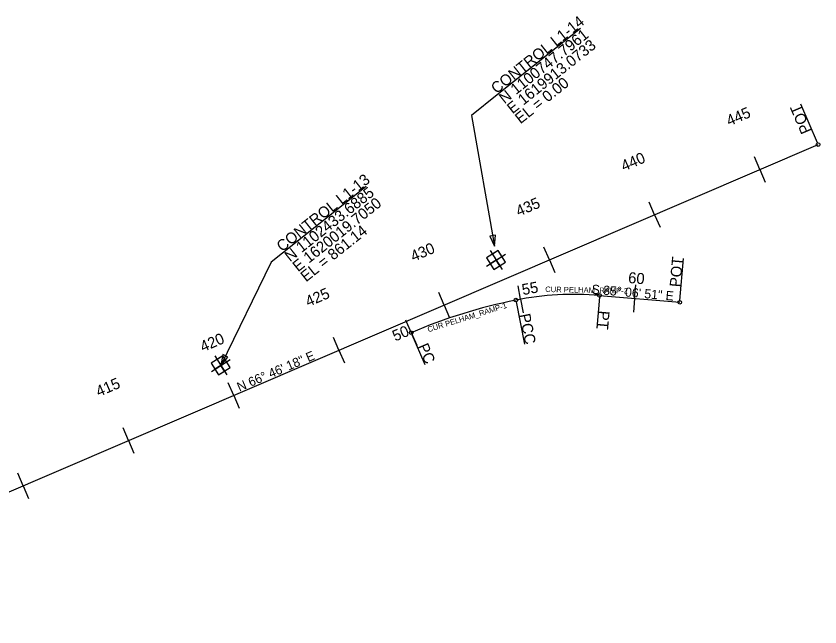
# Model space of a CAD drawing. Extents: x 1603447 to 1622636, y 1083818 to 1103958.
# Drawn here: x 1619126 to 1622636, y 1101292 to 1103958 of the extents above; entities that cross this region are included whole.
import ezdxf

# ---------------------------------------------------------------- set-up
doc = ezdxf.new("R2010")
doc.units = 0
for name, color, linetype in [('Level 1', 7, 'Continuous'), ('RD_HC_Points', 7, 'Continuous'), ('RD_HC_SUR_Bearing_TX400', 7, 'Continuous'), ('RD_HC_SUR_CL400', 7, 'Continuous'), ('RD_HC_SUR_PC_PT_400', 7, 'Continuous'), ('RD_HC_SUR_Tic400', 7, 'Continuous'), ('RD_HC_SUR_TX_Sta400', 7, 'Continuous'), ('RD_SHT_Misc1', 7, 'Continuous'), ('RD_TX_Misc1', 7, 'Continuous')]:
    doc.layers.add(name, color=color, linetype=linetype)

msp = doc.modelspace()

# ---------------------------------------------------------------- linework, layer by layer
at = {"layer": 'RD_HC_Points'}
for p, q in [((1621591, 1103903.8), (1621226.1, 1103613.6)), ((1620654.3, 1103213.8), (1620289.9, 1102924))]:
    msp.add_line(p, q, dxfattribs=at)
for points in [[(1621226.1, 1103613.6), (1621114.4, 1103524.7), (1621215.4, 1102954.1)], [(1620289.9, 1102924), (1620240.2, 1102884.4), (1620019.7, 1102433.7)]]:
    msp.add_lwpolyline(points, dxfattribs=at)
for points in [[(1621195.1, 1102997.6), (1621215.4, 1102954.1), (1621219.6, 1103002)], [(1620028.9, 1102480.8), (1620019.7, 1102433.7), (1620051.2, 1102469.9)]]:
    msp.add_lwpolyline(points, close=True, dxfattribs=at)
at = {"layer": 'RD_HC_SUR_CL400'}
for p, q in [((1617722.6, 1101292.3), (1622627.7, 1103397.5)), ((1621673.4, 1102738.7), (1622023.6, 1102708.8))]:
    msp.add_line(p, q, dxfattribs=at)
for centre, radius, start, end in [((1621562.7, 1101443.5), 1300, 85.1143, 101.2949), ((1621758.5, 1100462.8), 2300, 101.2949, 113.2284)]:
    msp.add_arc(centre, radius, start, end, dxfattribs=at)
at = {"layer": 'RD_HC_SUR_PC_PT_400'}
for p, q in [((1622624.6, 1103404.9), (1622552.2, 1103573.4)), ((1622024.3, 1102716.8), (1622039.9, 1102899.5)), ((1621672.7, 1102730.8), (1621661.2, 1102595.4)), ((1621309.6, 1102710.4), (1621346.4, 1102526.6)), ((1620854.6, 1102569), (1620911.3, 1102436.9))]:
    msp.add_line(p, q, dxfattribs=at)
for centre in [(1622627.7, 1103397.5), (1621308.1, 1102718.3), (1621673.4, 1102738.7), (1622023.6, 1102708.8), (1620851.4, 1102576.4)]:
    msp.add_circle(centre, 8, dxfattribs=at)
at = {"layer": 'RD_HC_SUR_Tic400'}
for p, q in [((1622557.3, 1103367.3), (1622557.3, 1103367.3)), ((1622373.5, 1103288.4), (1622349.8, 1103343.5)), ((1622465.4, 1103327.8), (1622465.4, 1103327.8)), ((1622373.5, 1103288.4), (1622397.2, 1103233.3)), ((1622281.6, 1103249), (1622281.6, 1103249)), ((1622189.7, 1103209.5), (1622189.7, 1103209.5)), ((1621914, 1103091.2), (1621890.4, 1103146.3)), ((1622097.8, 1103170.1), (1622097.8, 1103170.1)), ((1622005.9, 1103130.6), (1622005.9, 1103130.6)), ((1621914, 1103091.2), (1621937.7, 1103036.1)), ((1621822.1, 1103051.8), (1621822.1, 1103051.8)), ((1621730.2, 1103012.3), (1621730.2, 1103012.3)), ((1621638.4, 1102972.9), (1621638.4, 1102972.9)), ((1621454.6, 1102894), (1621430.9, 1102949.1)), ((1621454.6, 1102894), (1621478.2, 1102838.9)), ((1621328.7, 1102722.2), (1621317.9, 1102781.2)), ((1621826.7, 1102725.6), (1621831.8, 1102785.4)), ((1620995.1, 1102696.8), (1620971.4, 1102751.9)), ((1621826.7, 1102725.6), (1621821.6, 1102665.8)), ((1620995.1, 1102696.8), (1621018.8, 1102641.7)), ((1621328.7, 1102722.2), (1621339.5, 1102663.2)), ((1620851.4, 1102576.4), (1620827.8, 1102631.5)), ((1620535.6, 1102499.6), (1620512, 1102554.7)), ((1620719.4, 1102578.5), (1620719.4, 1102578.5)), ((1620851.4, 1102576.4), (1620875.1, 1102521.3)), ((1620627.5, 1102539.1), (1620627.5, 1102539.1)), ((1620535.6, 1102499.6), (1620559.3, 1102444.5)), ((1620443.7, 1102460.2), (1620443.7, 1102460.2)), ((1620351.8, 1102420.7), (1620351.8, 1102420.7)), ((1620259.9, 1102381.3), (1620259.9, 1102381.3)), ((1620076.2, 1102302.4), (1620052.5, 1102357.6)), ((1620168.1, 1102341.9), (1620168.1, 1102341.9)), ((1620076.2, 1102302.4), (1620099.8, 1102247.3)), ((1619984.3, 1102263), (1619984.3, 1102263)), ((1619892.4, 1102223.5), (1619892.4, 1102223.5)), ((1619800.5, 1102184.1), (1619800.5, 1102184.1)), ((1619616.7, 1102105.2), (1619593, 1102160.4)), ((1619708.6, 1102144.7), (1619708.6, 1102144.7)), ((1619616.7, 1102105.2), (1619640.4, 1102050.1)), ((1619524.8, 1102065.8), (1619524.8, 1102065.8)), ((1619432.9, 1102026.3), (1619432.9, 1102026.3)), ((1619341, 1101986.9), (1619341, 1101986.9)), ((1619157.2, 1101908), (1619133.6, 1101963.2)), ((1619249.1, 1101947.5), (1619249.1, 1101947.5)), ((1619157.2, 1101908), (1619180.9, 1101852.9))]:
    msp.add_line(p, q, dxfattribs=at)
at = {"layer": 'RD_SHT_Misc1'}
for p, q in [((1621195.6, 1102934.4), (1621248, 1102852.2)), ((1621180.7, 1102867.1), (1621262.9, 1102919.6)), ((1621205.6, 1102918.6), (1621221.8, 1102893.3)), ((1621221.8, 1102893.3), (1621247.1, 1102909.5)), ((1621221.8, 1102893.3), (1621196.5, 1102877.2)), ((1621237.9, 1102868), (1621221.8, 1102893.3)), ((1619978.6, 1102407.5), (1620060.8, 1102459.9)), ((1619993.5, 1102474.8), (1620045.9, 1102392.6)), ((1620003.6, 1102459), (1620019.7, 1102433.7)), ((1620019.7, 1102433.7), (1620045, 1102449.8)), ((1620019.7, 1102433.7), (1619994.4, 1102417.6)), ((1620035.8, 1102408.4), (1620019.7, 1102433.7))]:
    msp.add_line(p, q, dxfattribs=at)
for points in [[(1621212.6, 1102851.9), (1621263.2, 1102884.2), (1621230.9, 1102934.8), (1621180.4, 1102902.5)], [(1620010.6, 1102392.3), (1620061.1, 1102424.5), (1620028.9, 1102475.1), (1619978.3, 1102442.8)]]:
    msp.add_lwpolyline(points, close=True, dxfattribs=at)
for points in [[(1621247.1, 1102909.5), (1621230.9, 1102934.8), (1621205.6, 1102918.6)], [(1621196.5, 1102877.2), (1621212.6, 1102851.9)], [(1621212.6, 1102851.9), (1621237.9, 1102868)], [(1620045, 1102449.8), (1620028.9, 1102475.1), (1620003.6, 1102459)], [(1619994.4, 1102417.6), (1620010.6, 1102392.3)], [(1620010.6, 1102392.3), (1620035.8, 1102408.4)]]:
    msp.add_lwpolyline(points, dxfattribs=at)

# ---------------------------------------------------------------- texts
at = {"layer": 'Level 1'}
for s, rotation, p in [('445', 23.2284, (1622239.6, 1103476.9)), ('435', 23.2284, (1621320.6, 1103082.5)), ('55', 10.3711, (1621339, 1102740)), ('425', 23.2284, (1620401.7, 1102688.1)), ('415', 23.2284, (1619487, 1102295.5))]:
    msp.add_text(s, height=48, rotation=rotation, dxfattribs=at).set_placement(p)
at = {"layer": 'RD_HC_Points'}
for s, p in [('CONTROL L1-14', (1621223.7, 1103616.8)), ('N 1100747.7961', (1621258.5, 1103572.9)), ('E 1619913.0733', (1621293.4, 1103529.1)), ('EL = 0.00', (1621328.2, 1103485.3)), ('CONTROL L1-13', (1620287.5, 1102927.1)), ('N 1102433.6885', (1620322.3, 1102883.3)), ('E 1620019.7050', (1620357.2, 1102839.5)), ('EL = 861.14', (1620392, 1102795.6))]:
    msp.add_text(s, height=48, rotation=38.4995, dxfattribs=at).set_placement(p)
at = {"layer": 'RD_HC_SUR_Bearing_TX400'}
for s, rotation, p in [('S 85%%d 06\' 51" E', 355.1143, (1621637.7, 1102746.8)), ('N 66%%d 46\' 18" E', 23.2284, (1620101.2, 1102318.6))]:
    msp.add_text(s, height=40, rotation=rotation, dxfattribs=at).set_placement(p)
at = {"layer": 'RD_HC_SUR_PC_PT_400'}
for s, rotation, p in [('POT', 113.2284, (1622600.2, 1103456.5)), ('POT', 85.1143, (1622027.1, 1102773.7)), ('PCC', 281.2949, (1621322.8, 1102654.9)), ('PT', 265.1143, (1621669.9, 1102673.8)), ('PC', 293.2284, (1620878.9, 1102517.4))]:
    msp.add_text(s, height=48, rotation=rotation, dxfattribs=at).set_placement(p)
at = {"layer": 'RD_HC_SUR_TX_Sta400'}
for s, rotation, p in [('440', 23.2284, (1621779.8, 1103279.5)), ('430', 23.2284, (1620860.9, 1102885.2)), ('60', 355.1143, (1621797.1, 1102793.4)), ('50', 23.2284, (1620781.5, 1102537.5)), ('420', 23.2284, (1619942, 1102490.8))]:
    msp.add_text(s, height=48, rotation=rotation, dxfattribs=at).set_placement(p)
at = {"layer": 'RD_TX_Misc1'}
for s, rotation, p in [('CUR PELHAM_RAMP-2', 358.9153, (1621436.3, 1102753.9)), ('CUR PELHAM_RAMP-1', 17.2633, (1620926.4, 1102578.1))]:
    msp.add_text(s, height=24, rotation=rotation, dxfattribs=at).set_placement(p)

doc.saveas('drawing.dxf')
